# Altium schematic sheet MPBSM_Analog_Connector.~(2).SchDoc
size 431 x 279 mm; Date: Not shown in title block; ApprovedBy: Not shown in title block; CheckedBy: Not shown in title block; Author: Not shown in title block; CompanyName: Not shown in title block; Engineer: Not shown in title block; Organization: Not shown in title block; Address1: Not shown in title block; Address2: Not shown in title block; Address3: Not shown in title block; Address4: Not shown in title block; DocumentNumber: 1; Revision: Use project parameter SCH_Rev; SheetNumber: 2; SheetTotal: 3; PageSetup: Record=PageOptions¦CenterHorizontal=True¦CenterVertical=True¦PrintScale=1.00¦XCorrection=1.00¦YCorrection=1.00¦PrintKind=0¦BorderSize=5000000¦LeftOffset=0¦BottomOffset=0¦Orientation=2¦PaperLength=1000¦PaperWidth=1000¦Scale=100¦PaperSource=15¦PrintQuality=600¦MediaType=1¦DitherType=10¦PaperKind=Letter¦PrintScaleMode=1
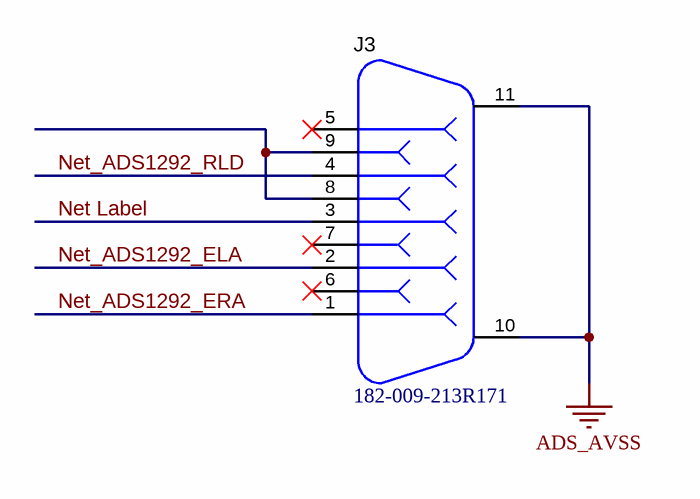
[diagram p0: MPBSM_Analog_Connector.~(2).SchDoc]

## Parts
J3  182-009-213R171  [NORCOMP_182-009-213R171]

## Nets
ADS_AVSS: J3.10 J3.11
Net Label: J3.3
Net_ADS1292_ELA: J3.2
Net_ADS1292_ERA: J3.1
Net_ADS1292_RLD: J3.4
NetJ3_8: J3.8 J3.9

Not connected (* = marked no-connect by the designer): J3 5* 6* 7*

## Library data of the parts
J3 = 182-009-213R171: CONN DB9 FEMALE R/A SOLDER TH; Manufacturer: NorComp; SymbolCreator: a0412235; CompType: Connector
